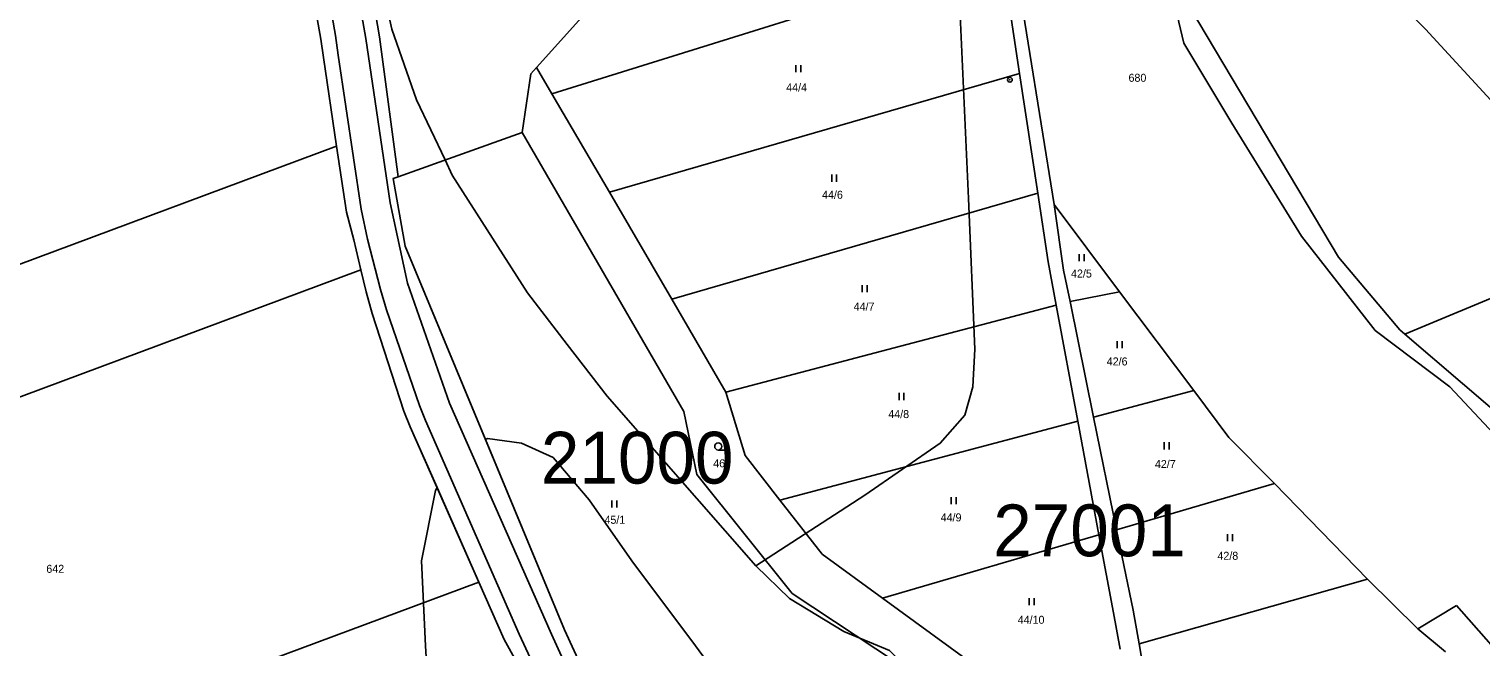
# Model space of a CAD drawing. Extents: x -725765 to -723182, y -1052705 to -1049154.
# Drawn here: x -725049.2 to -724740.7, y -1050513.3 to -1050382 of the extents above; entities that cross this region are included whole.
import ezdxf

# ---------------------------------------------------------------- set-up
doc = ezdxf.new("R2010")
doc.units = 0
for name, color, linetype in [('Vrstva 1', 7, 'Continuous'), ('Vrstva 18', 7, 'Continuous'), ('Vrstva 25', 7, 'Continuous'), ('Vrstva 4', 7, 'Continuous'), ('Vrstva 52', 7, 'Continuous'), ('Vrstva 53', 7, 'Continuous')]:
    doc.layers.add(name, color=color, linetype=linetype)

msp = doc.modelspace()

# ---------------------------------------------------------------- linework, layer by layer
at = {"layer": 'Vrstva 1'}
for points in [[(-724494.68, -1050337.48), (-724756.91, -1050446.8)], [(-724974.8, -1050383.63), (-724981.17, -1050346.3)], [(-724993.47, -1050349.06), (-724987.22, -1050384.11)], [(-724831.39, -1050419.25), (-724842.44, -1050350.62)], [(-724938.14, -1050395.74), (-724842.62, -1050365.92)], [(-724842.62, -1050365.92), (-724838.76, -1050391.39)], [(-724941.4, -1050390.14), (-724929.23, -1050376.61)], [(-724771.01, -1050430.44), (-724802.44, -1050377.62)], [(-724987.22, -1050384.11), (-724986.69, -1050388.01)], [(-724970.83, -1050413.34), (-724974.8, -1050383.63)], [(-724986.69, -1050388.01), (-724983.87, -1050406.88)], [(-724942.58, -1050391.46), (-724941.4, -1050390.14)], [(-724941.4, -1050390.14), (-724938.14, -1050395.74)], [(-724925.93, -1050416.66), (-724838.76, -1050391.39)], [(-724838.76, -1050391.39), (-724834.9, -1050416.87)], [(-724942.58, -1050391.46), (-724944.43, -1050403.98)], [(-724938.14, -1050395.74), (-724925.93, -1050416.66)], [(-724944.43, -1050403.98), (-724970.83, -1050413.34)], [(-724944.43, -1050403.98), (-724910.14, -1050463.25)], [(-724983.87, -1050406.88), (-725199.44, -1050487.16)], [(-724983.87, -1050406.88), (-724981.78, -1050420.89)], [(-724970.83, -1050413.34), (-724971.83, -1050413.7)], [(-724971.83, -1050413.7), (-724969.28, -1050428.13)], [(-724925.93, -1050416.66), (-724912.69, -1050439.35)], [(-724912.69, -1050439.35), (-724834.9, -1050416.87)], [(-724834.9, -1050416.87), (-724832.69, -1050431.43)], [(-724980.23, -1050426.78), (-724981.78, -1050420.89)], [(-724817.51, -1050437.78), (-724831.39, -1050419.25)], [(-724831.39, -1050419.25), (-724829.43, -1050433.19), (-724828.06, -1050439.87)], [(-724980.23, -1050426.78), (-724978.7, -1050433.17)], [(-724969.28, -1050428.13), (-724935.49, -1050509.61)], [(-724832.69, -1050431.43), (-724830.98, -1050440.64)], [(-724757.98, -1050445.88), (-724771.01, -1050430.44)], [(-724978.7, -1050433.17), (-725190.59, -1050512.08)], [(-724978.7, -1050433.17), (-724977.59, -1050437.79)], [(-724976.3, -1050442.39), (-724977.59, -1050437.79)], [(-724912.69, -1050439.35), (-724901.16, -1050459.11)], [(-724901.16, -1050459.11), (-724830.98, -1050440.64)], [(-724830.98, -1050440.64), (-724826.39, -1050465.3)], [(-724828.06, -1050439.87), (-724817.51, -1050437.78)], [(-724828.06, -1050439.87), (-724823.05, -1050464.42)], [(-724801.77, -1050458.79), (-724817.51, -1050437.78)], [(-724969.57, -1050463.18), (-724976.3, -1050442.39)], [(-724756.91, -1050446.8), (-724757.98, -1050445.88)], [(-724720.19, -1050478.25), (-724756.91, -1050446.8)], [(-724901.16, -1050459.11), (-724897.1, -1050472.57)], [(-724823.05, -1050464.42), (-724801.77, -1050458.79)], [(-724794.28, -1050468.78), (-724801.77, -1050458.79)], [(-724968.25, -1050466.49), (-724969.57, -1050463.18)], [(-724910.14, -1050463.25), (-724907.38, -1050476.66)], [(-724889.69, -1050482.05), (-724826.39, -1050465.3)], [(-724826.39, -1050465.3), (-724821.9, -1050489.44)], [(-724823.05, -1050464.42), (-724818.16, -1050488.35)], [(-724953.68, -1050499.49), (-724968.25, -1050466.49)], [(-724784.64, -1050478.56), (-724794.28, -1050468.78)], [(-724897.1, -1050472.57), (-724889.69, -1050482.05)], [(-724907.38, -1050476.66), (-724887.09, -1050501.94)], [(-724818.16, -1050488.35), (-724784.64, -1050478.56)], [(-724764.88, -1050498.84), (-724784.64, -1050478.56)], [(-724889.69, -1050482.05), (-724880.71, -1050493.52)], [(-724867.91, -1050502.87), (-724821.9, -1050489.44)], [(-724821.9, -1050489.44), (-724818.81, -1050506.01)], [(-724818.16, -1050488.35), (-724814.67, -1050505.42)], [(-724880.71, -1050493.52), (-724867.91, -1050502.87)], [(-724813.39, -1050512.61), (-724764.88, -1050498.84)], [(-724754.16, -1050509.45), (-724764.88, -1050498.84)], [(-724953.68, -1050499.49), (-725166.88, -1050578.89)], [(-724948.28, -1050511.7), (-724953.68, -1050499.49)], [(-724887.09, -1050501.94), (-724855.9, -1050522.55)], [(-724867.91, -1050502.87), (-724846.69, -1050518.36)], [(-724814.67, -1050505.42), (-724813.39, -1050512.61)], [(-724745.93, -1050504.49), (-724754.16, -1050509.45)], [(-724738.58, -1050512.81), (-724745.93, -1050504.49)], [(-724818.81, -1050506.01), (-724817.39, -1050513.74)], [(-724945.76, -1050516.26), (-724948.28, -1050511.7)], [(-724935.49, -1050509.61), (-724928.9, -1050523.96)], [(-724754.16, -1050509.45), (-724748.28, -1050514.34)], [(-724813.39, -1050512.61), (-724812, -1050520.46)]]:
    msp.add_lwpolyline(points, dxfattribs=at)
at = {"layer": 'Vrstva 25'}
for points in [[(-724886.32, -1050391.14), (-724886.32, -1050389.64)], [(-724885.28, -1050391.14), (-724885.28, -1050389.64)], [(-724878.68, -1050414.4), (-724878.68, -1050412.9)], [(-724877.64, -1050414.4), (-724877.64, -1050412.9)], [(-724826.09, -1050431.31), (-724826.09, -1050429.81)], [(-724825.05, -1050431.31), (-724825.05, -1050429.81)], [(-724872.21, -1050437.86), (-724872.21, -1050436.36)], [(-724871.17, -1050437.86), (-724871.17, -1050436.36)], [(-724818.01, -1050449.81), (-724818.01, -1050448.31)], [(-724816.97, -1050449.81), (-724816.97, -1050448.31)], [(-724864.37, -1050460.8), (-724864.37, -1050459.3)], [(-724863.33, -1050460.8), (-724863.33, -1050459.3)], [(-724902.8, -1050471.42), (-724901.05, -1050471.42)], [(-724808.03, -1050471.28), (-724808.03, -1050469.78)], [(-724806.99, -1050471.28), (-724806.99, -1050469.78)], [(-724925.41, -1050483.64), (-724925.41, -1050482.14)], [(-724924.37, -1050483.64), (-724924.37, -1050482.14)], [(-724853.28, -1050482.94), (-724853.28, -1050481.44)], [(-724852.24, -1050482.94), (-724852.24, -1050481.44)], [(-724794.58, -1050490.82), (-724794.58, -1050489.32)], [(-724793.54, -1050490.82), (-724793.54, -1050489.32)], [(-724836.71, -1050504.42), (-724836.71, -1050502.92)], [(-724835.67, -1050504.42), (-724835.67, -1050502.92)]]:
    msp.add_lwpolyline(points, dxfattribs=at)
for centre, radius in [((-724840.83, -1050392.75), 0.5), ((-724840.83, -1050392.75), 0.032), ((-724902.8, -1050470.67), 0.75)]:
    msp.add_circle(centre, radius, dxfattribs=at)
at = {"layer": 'Vrstva 4'}
for points in [[(-724977.7, -1050383.99), (-724984.14, -1050347.26)], [(-724990.12, -1050348.93), (-724984.14, -1050383.34)], [(-724984.14, -1050383.34), (-724983.52, -1050387.52)], [(-724972.47, -1050418.93), (-724977.7, -1050383.99)], [(-724983.52, -1050387.52), (-724978.64, -1050420.27)], [(-724968.8, -1050435.96), (-724972.47, -1050418.93)], [(-724978.64, -1050420.27), (-724977.33, -1050426.65)], [(-724977.33, -1050426.65), (-724974.59, -1050437.32)], [(-724974.59, -1050437.32), (-724973.25, -1050441.64)], [(-724959.87, -1050461.44), (-724968.8, -1050435.96)], [(-724973.25, -1050441.64), (-724966.29, -1050461.98)], [(-724966.29, -1050461.98), (-724965, -1050465.16)], [(-724938.23, -1050510.56), (-724959.87, -1050461.44)], [(-724965, -1050465.16), (-724945.06, -1050510.57)], [(-724945.06, -1050510.57), (-724942.72, -1050515.75)], [(-724932.61, -1050522.85), (-724938.23, -1050510.56)]]:
    msp.add_lwpolyline(points, dxfattribs=at)
at = {"layer": 'Vrstva 52'}
for points in [[(-725042.59, -1050197.01), (-725034.47, -1050214.49), (-725028.58, -1050225.24), (-725012.45, -1050256.75), (-724993.31, -1050299.29), (-724990.73, -1050307.79), (-724986.04, -1050323.28), (-724981.17, -1050346.3), (-724974.8, -1050383.63), (-724970.83, -1050413.34), (-724971.83, -1050413.7), (-724969.28, -1050428.13), (-724952.25, -1050469.19)], [(-725042.59, -1050197.01), (-725035.81, -1050206), (-725012.81, -1050230), (-725000, -1050244.83), (-724998.13, -1050247), (-724985.81, -1050263), (-724981.19, -1050275), (-724977, -1050297), (-724974.31, -1050317), (-724976.38, -1050346), (-724975.5, -1050367), (-724972.13, -1050382), (-724966.88, -1050397), (-724960.83, -1050409.79), (-724959.31, -1050413), (-724943.31, -1050438), (-724934.88, -1050449), (-724926.38, -1050460), (-724894.81, -1050496)], [(-724814.63, -1050317), (-724814.31, -1050319), (-724809.69, -1050358), (-724806.69, -1050373), (-724803.88, -1050385), (-724793.69, -1050402), (-724778.88, -1050426), (-724763.19, -1050446), (-724747.38, -1050458), (-724728.63, -1050478), (-724711.63, -1050498), (-724701.38, -1050511), (-724691.69, -1050524), (-724684.13, -1050518), (-724673.88, -1050537), (-724662.19, -1050558), (-724649, -1050579), (-724638.63, -1050600), (-724637.91, -1050601.39), (-724635, -1050607)], [(-724506.66, -1050694.97), (-724493.31, -1050690), (-724485.63, -1050684), (-724481.81, -1050678), (-724483.13, -1050666), (-724485.63, -1050658), (-724492.69, -1050650), (-724527.88, -1050622), (-724562.38, -1050591), (-724598.31, -1050561), (-724618.38, -1050543), (-724647.31, -1050511), (-724667.69, -1050488), (-724701.63, -1050439), (-724731.38, -1050405), (-724752.5, -1050382), (-724783.31, -1050351), (-724814.63, -1050317)], [(-724993.47, -1050349.06), (-724987.22, -1050384.11), (-724986.69, -1050388.01), (-724983.87, -1050406.88), (-724981.78, -1050420.89), (-724980.23, -1050426.78), (-724978.7, -1050433.17), (-724977.59, -1050437.79), (-724976.3, -1050442.39), (-724969.57, -1050463.18), (-724968.25, -1050466.49), (-724962.55, -1050479.39)], [(-724740.39, -1050641.69), (-724749.44, -1050613.49), (-724747.91, -1050601.21), (-724753.79, -1050580.49), (-724762.08, -1050566.41), (-724763.01, -1050564.95), (-724778.48, -1050540.74), (-724792.94, -1050538.33), (-724798.58, -1050533.8), (-724801.64, -1050531.34), (-724812, -1050520.46), (-724813.39, -1050512.61), (-724814.67, -1050505.42), (-724818.16, -1050488.35), (-724823.05, -1050464.42), (-724828.06, -1050439.87), (-724829.43, -1050433.19), (-724831.39, -1050419.25), (-724842.44, -1050350.62)], [(-724817.39, -1050513.74), (-724818.81, -1050506.01), (-724821.9, -1050489.44), (-724826.39, -1050465.3), (-724830.98, -1050440.64), (-724832.69, -1050431.43), (-724834.9, -1050416.87), (-724838.76, -1050391.39), (-724842.62, -1050365.92)], [(-724894.81, -1050496), (-724871.63, -1050481), (-724855.63, -1050470), (-724850.38, -1050464), (-724848.69, -1050458), (-724848.31, -1050450), (-724849.63, -1050418), (-724851.38, -1050379)], [(-724952.25, -1050469.19), (-724951.81, -1050469), (-724944.63, -1050470), (-724937.88, -1050473), (-724930.19, -1050482), (-724921.13, -1050495), (-724907.63, -1050513), (-724898.13, -1050526), (-724884.13, -1050555), (-724877.38, -1050572), (-724874.17, -1050580.35)], [(-724952.25, -1050469.19), (-724935.49, -1050509.61), (-724928.9, -1050523.96), (-724925.5, -1050531.34), (-724921.56, -1050546.38), (-724916.3, -1050557.27), (-724912.91, -1050561.61), (-724905.62, -1050570.94), (-724889.02, -1050585.83), (-724880.1, -1050591.04), (-724878.18, -1050585.58), (-724874.17, -1050580.35)], [(-724962.55, -1050479.39), (-724962.88, -1050480), (-724965.81, -1050495), (-724965, -1050513), (-724964.31, -1050525), (-724964.03, -1050529.59), (-724962.38, -1050556), (-724960.72, -1050567.87)], [(-724960.72, -1050567.87), (-724928.41, -1050566.61), (-724922.05, -1050564.84), (-724927.41, -1050553.28), (-724925.99, -1050552.71), (-724927.71, -1050547.24), (-724931.58, -1050534.9), (-724936.56, -1050525.18), (-724931.9, -1050524.44), (-724937.51, -1050525.33), (-724939.48, -1050525.65), (-724943.41, -1050526.29), (-724945.76, -1050516.26), (-724948.28, -1050511.7), (-724953.68, -1050499.49), (-724962.55, -1050479.39)], [(-724894.81, -1050496), (-724887.63, -1050503), (-724876.13, -1050510), (-724866.38, -1050514), (-724859.38, -1050521), (-724852.38, -1050530), (-724846.92, -1050540.04)]]:
    msp.add_lwpolyline(points, dxfattribs=at)

# ---------------------------------------------------------------- texts
at = {"layer": 'Vrstva 18'}
for s, p in [('44/4', (-724888.36, -1050395.22)), ('680', (-724815.63, -1050393.17)), ('44/6', (-724880.74, -1050418.03)), ('42/5', (-724827.84, -1050434.77)), ('44/7', (-724874.03, -1050441.8)), ('42/6', (-724820.26, -1050453.45)), ('44/8', (-724866.67, -1050464.64)), ('46', (-724903.86, -1050475.1)), ('42/7', (-724810.02, -1050475.25)), ('45/1', (-724926.97, -1050487.1)), ('44/9', (-724855.54, -1050486.59)), ('42/8', (-724796.74, -1050494.75)), ('642', (-725045.56, -1050497.52)), ('44/10', (-724839.17, -1050508.35))]:
    msp.add_text(s, height=1.7, dxfattribs=at).set_placement(p)
at = {"layer": 'Vrstva 53'}
for s, p in [('21000', (-724940.47, -1050478.55)), ('27001', (-724844.37, -1050494))]:
    msp.add_text(s, height=11, dxfattribs=at).set_placement(p)

doc.saveas('drawing.dxf')
